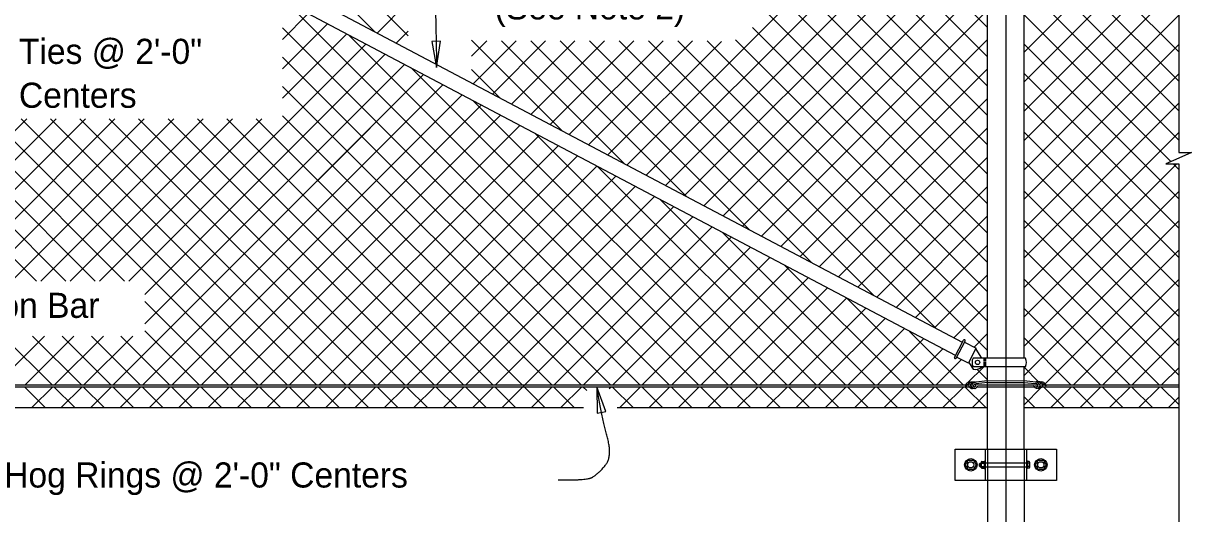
# Model space of a CAD drawing. Extents: x 0 to 41.1, y 0 to 25.9.
# Drawn here: x 6.74 to 16.11, y 16.37 to 20.31 of the extents above; entities that cross this region are included whole.
import ezdxf

# ---------------------------------------------------------------- set-up
doc = ezdxf.new("R2010")
doc.units = 0
for name, color, linetype in [('CL_Major', 7, 'Continuous'), ('Dimension', 7, 'Continuous'), ('Miscellaneous', 7, 'Continuous'), ('SteelMisc', 7, 'Continuous'), ('SteelMisc_h', 7, 'Continuous'), ('SupstrConc', 7, 'Continuous'), ('TextStructures', 7, 'Continuous')]:
    doc.layers.add(name, color=color, linetype=linetype)

msp = doc.modelspace()

# ---------------------------------------------------------------- linework, layer by layer
at = {"layer": 'CL_Major'}
msp.add_line((14.615, 25.0052), (14.615, 15.2584), dxfattribs=at)
at = {"layer": 'Dimension'}
for points in [[(16.002, 23.2265), (16.002, 21.2702), (16.1053, 21.2702), (16.002, 21.2252), (15.8987, 21.1802), (16.002, 21.1802), (16.002, 20.2867)], [(16.002, 20.2867), (16.002, 19.2689), (16.1053, 19.2689), (16.002, 19.2239), (15.8987, 19.1789), (16.002, 19.1789), (16.002, 16.9746)], [(16.002, 17.2246), (16.002, 15.3737), (16.1053, 15.3737), (16.002, 15.3287), (15.8987, 15.2837), (16.002, 15.2837), (16.002, 13.2829)]]:
    msp.add_lwpolyline(points, dxfattribs=at)
for points in [[(10.0503, 19.9529), (10.0815, 20.1618), (10.011, 20.1604)], [(11.336, 17.3912), (11.3376, 17.18), (11.4071, 17.1923)]]:
    msp.add_lwpolyline(points, close=True, dxfattribs=at)
for points in [[(6.6174, 20.081), (6.4865, 20.0669), (6.3036, 20.1341), (6.3121, 20.4608), (6.945, 21.4806)], [(10.4281, 20.8052), (10.1586, 20.8133), (10.0405, 20.6549), (10.0376, 20.5337), (10.0422, 20.3659), (10.0503, 19.9529)], [(11.0247, 16.6442), (11.2476, 16.6407), (11.3325, 16.6797), (11.4633, 16.8284), (11.3785, 17.1258), (11.336, 17.3911)]]:
    msp.add_open_spline(points, degree=2, dxfattribs=at)
at = {"layer": 'Miscellaneous'}
for p, q in [((6.7499, 23.0431), (9.5571, 20.2359)), ((6.9856, 23.0431), (9.8224, 20.2063)), ((10.5211, 23.0431), (14.4692, 19.095)), ((10.7568, 23.0431), (14.4692, 19.3307)), ((10.9925, 23.0431), (14.4692, 19.5664)), ((11.2282, 23.0431), (14.4692, 19.8021)), ((11.4639, 23.0431), (14.4692, 20.0378)), ((11.6996, 23.0431), (14.4692, 20.2735)), ((11.5767, 19.1686), (14.4692, 22.0611)), ((11.7309, 19.0871), (14.4692, 21.8254)), ((11.8851, 19.0056), (14.4692, 21.5897)), ((12.0393, 18.9241), (14.4692, 21.354)), ((14.7609, 21.318), (16.002, 20.0769)), ((14.7609, 20.0738), (16.002, 21.3149)), ((4.8859, 21.1359), (8.6158, 17.4059)), ((12.1936, 18.8426), (14.4692, 21.1183)), ((14.7609, 21.0823), (16.002, 19.8412)), ((14.7609, 19.8381), (16.002, 21.0792)), ((4.8859, 20.9002), (7.5472, 18.2388)), ((12.3478, 18.7611), (14.4692, 20.8826)), ((14.7609, 20.8466), (16.002, 19.6055)), ((14.7609, 19.6024), (16.002, 20.8435)), ((4.8859, 20.6644), (7.3115, 18.2388)), ((12.502, 18.6796), (14.4692, 20.6469)), ((12.6449, 20.6836), (14.4692, 18.8593)), ((14.7609, 20.6109), (16.002, 19.3698)), ((14.7609, 19.3667), (16.002, 20.6078)), ((4.8859, 20.4287), (7.0758, 18.2388)), ((8.845, 20.4766), (11.9157, 17.4059)), ((9.572, 20.228), (9.8224, 20.4784)), ((12.6214, 20.4714), (14.4692, 18.6236)), ((8.8145, 20.1777), (9.0206, 20.3838)), ((12.6562, 18.5982), (14.4692, 20.4112)), ((14.7609, 20.3752), (15.9395, 19.1966)), ((14.7609, 19.131), (16.002, 20.3721)), ((8.8145, 19.942), (9.1748, 20.3023)), ((8.8145, 20.2713), (11.68, 17.4059)), ((9.7262, 20.1465), (9.8224, 20.2427)), ((12.5832, 20.2739), (14.4692, 18.3879)), ((4.8876, 20.1913), (6.8401, 18.2388)), ((8.8145, 19.7063), (9.3291, 20.2208)), ((9.3449, 20.2124), (12.1514, 17.4059)), ((10.3288, 20.1713), (11.0567, 19.4434)), ((10.3288, 20.042), (10.4524, 20.1656)), ((10.343, 19.8205), (10.6881, 20.1656)), ((10.4973, 19.7391), (10.9238, 20.1656)), ((10.5702, 20.1656), (11.5565, 19.1793)), ((10.6515, 19.6576), (11.1595, 20.1656)), ((10.8057, 19.5761), (11.3952, 20.1656)), ((10.8059, 20.1656), (12.0564, 18.9151)), ((10.9599, 19.4946), (11.6309, 20.1656)), ((11.0416, 20.1656), (12.5562, 18.651)), ((11.1141, 19.4131), (11.8666, 20.1656)), ((11.2683, 19.3316), (12.1023, 20.1656)), ((11.2773, 20.1656), (13.0561, 18.3868)), ((11.4225, 19.2501), (12.3341, 20.1616)), ((11.513, 20.1656), (13.5559, 18.1227)), ((11.7487, 20.1656), (14.0558, 17.8585)), ((11.9844, 20.1656), (14.4692, 17.6808)), ((12.2201, 20.1656), (14.4692, 17.9165)), ((12.4479, 20.1735), (14.4692, 18.1522)), ((12.8104, 18.5167), (14.4692, 20.1755)), ((7.5828, 18.2388), (9.4833, 20.1393)), ((7.7103, 18.1306), (9.6375, 20.0578)), ((14.7609, 20.1395), (16.002, 18.8984)), ((14.7609, 18.8953), (16.002, 20.1364)), ((7.7103, 17.8949), (9.7917, 19.9763)), ((8.8145, 20.0356), (11.4443, 17.4059)), ((9.0917, 19.2763), (9.7917, 19.9763)), ((7.457, 17.4059), (9.9459, 19.8948)), ((9.0917, 19.0406), (9.9459, 19.8948)), ((9.8447, 19.9483), (12.3871, 17.4059)), ((10.3288, 19.9356), (10.5568, 19.7076)), ((12.9646, 18.4352), (14.4692, 19.9398)), ((14.7609, 19.9038), (16.002, 18.6627)), ((14.7609, 18.6596), (16.002, 19.9007)), ((7.6927, 17.4059), (10.1001, 19.8133)), ((8.8145, 19.7999), (11.2086, 17.4059)), ((9.0917, 18.8049), (10.1001, 19.8133)), ((7.9284, 17.4059), (10.2543, 19.7318)), ((10.3445, 19.6841), (12.6228, 17.4059)), ((13.1188, 18.3537), (14.4692, 19.7041)), ((8.1641, 17.4059), (10.4085, 19.6503)), ((14.7609, 19.6681), (16.002, 18.427)), ((14.7609, 18.4239), (16.002, 19.665)), ((5.7273, 18.5047), (6.7626, 19.54)), ((5.8187, 18.3603), (6.9983, 19.54)), ((5.9329, 18.2388), (7.234, 19.54)), ((6.1686, 18.2388), (7.4697, 19.54)), ((6.4043, 18.2388), (7.7055, 19.54)), ((6.64, 18.2388), (7.9412, 19.54)), ((6.7175, 19.54), (8.8515, 17.4059)), ((6.8757, 18.2388), (8.1769, 19.54)), ((6.9532, 19.54), (9.0872, 17.4059)), ((7.1114, 18.2388), (8.4126, 19.54)), ((7.1889, 19.54), (9.3229, 17.4059)), ((7.3471, 18.2388), (8.6483, 19.54)), ((7.4246, 19.54), (9.5586, 17.4059)), ((7.6603, 19.54), (9.7943, 17.4059)), ((7.896, 19.54), (10.03, 17.4059)), ((8.1317, 19.54), (10.2657, 17.4059)), ((8.3674, 19.54), (10.5014, 17.4059)), ((8.3998, 17.4059), (10.5627, 19.5688)), ((8.6031, 19.54), (10.7372, 17.4059)), ((8.8145, 19.5642), (10.9729, 17.4059)), ((8.6355, 17.4059), (10.717, 19.4873)), ((8.8712, 17.4059), (10.8712, 19.4059)), ((10.8444, 19.42), (12.8585, 17.4059)), ((13.273, 18.2722), (14.4692, 19.4684)), ((14.7609, 19.4324), (16.002, 18.1913)), ((14.7609, 18.1882), (16.002, 19.4293)), ((9.1069, 17.4059), (11.0254, 19.3244)), ((9.3426, 17.4059), (11.1796, 19.2429)), ((13.4272, 18.1907), (14.4692, 19.2327)), ((9.5783, 17.4059), (11.3338, 19.1614)), ((11.3442, 19.1559), (13.0942, 17.4059)), ((14.7609, 19.1967), (16.002, 17.9556)), ((14.7609, 17.9525), (15.9873, 19.1789)), ((15.9572, 19.1789), (16.002, 19.1341)), ((9.814, 17.4059), (11.488, 19.0799)), ((10.0497, 17.4059), (11.6422, 18.9984)), ((13.5814, 18.1092), (14.4692, 18.997)), ((14.7609, 18.961), (16.002, 17.7199)), ((14.7609, 17.7168), (16.002, 18.9578)), ((10.2854, 17.4059), (11.7964, 18.9169)), ((10.5211, 17.4059), (11.9506, 18.8354)), ((11.8441, 18.8917), (13.3299, 17.4059)), ((10.639, 17.2881), (12.1048, 18.7539)), ((13.7356, 18.0277), (14.4692, 18.7613)), ((10.9925, 17.4059), (12.2591, 18.6724)), ((14.7609, 18.7253), (16.002, 17.4842)), ((14.7609, 17.4811), (16.002, 18.7221)), ((11.2282, 17.4059), (12.4133, 18.5909)), ((12.3439, 18.6276), (13.5656, 17.4059)), ((11.4639, 17.4059), (12.5675, 18.5094)), ((13.8899, 17.9462), (14.4692, 18.5256)), ((14.7609, 18.4896), (15.8446, 17.4059)), ((14.9303, 17.4148), (16.002, 18.4864)), ((11.6996, 17.4059), (12.7217, 18.428)), ((11.9353, 17.4059), (12.8759, 18.3465)), ((12.8437, 18.3635), (13.8013, 17.4059)), ((14.0441, 17.8647), (14.4692, 18.2899)), ((12.1711, 17.4059), (13.0301, 18.265)), ((12.4068, 17.4059), (13.1843, 18.1835)), ((14.7609, 18.2539), (15.6089, 17.4059)), ((15.1572, 17.4059), (16.002, 18.2507)), ((12.6425, 17.4059), (13.3385, 18.102)), ((13.3436, 18.0993), (14.037, 17.4059)), ((7.7103, 18.0757), (8.3801, 17.4059)), ((12.8782, 17.4059), (13.4927, 18.0205)), ((14.1983, 17.7832), (14.4692, 18.0542)), ((14.7609, 18.0182), (15.3732, 17.4059)), ((15.3929, 17.4059), (16.002, 18.015)), ((13.1139, 17.4059), (13.647, 17.939)), ((7.7103, 17.84), (8.1444, 17.4059)), ((13.3496, 17.4059), (13.8012, 17.8575)), ((13.8434, 17.8352), (14.2727, 17.4059)), ((14.36, 17.7093), (14.4692, 17.8185)), ((6.5142, 17.4059), (6.9059, 17.7976)), ((6.5742, 17.7976), (6.9659, 17.4059)), ((6.7499, 17.4059), (7.1416, 17.7976)), ((6.8099, 17.7976), (7.2016, 17.4059)), ((6.9856, 17.4059), (7.3773, 17.7976)), ((7.0456, 17.7976), (7.4373, 17.4059)), ((7.2213, 17.4059), (7.613, 17.7976)), ((7.2813, 17.7976), (7.673, 17.4059)), ((7.517, 17.7976), (7.9087, 17.4059)), ((13.5853, 17.4059), (13.9554, 17.776)), ((14.7609, 17.7825), (15.1375, 17.4059)), ((15.6286, 17.4059), (16.002, 17.7793)), ((13.821, 17.4059), (14.1096, 17.6945)), ((14.0567, 17.4059), (14.2591, 17.6084)), ((14.3083, 17.4218), (14.4379, 17.5514)), ((14.3836, 17.5307), (14.4692, 17.4451)), ((14.7609, 17.5468), (14.8783, 17.4294)), ((15.8643, 17.4059), (16.002, 17.5436)), ((6.745, 17.3912), (6.9116, 17.2245)), ((6.8042, 17.2245), (6.9709, 17.3912)), ((6.9807, 17.3912), (7.1473, 17.2245)), ((7.0399, 17.2245), (7.2066, 17.3912)), ((7.2164, 17.3912), (7.383, 17.2245)), ((7.2756, 17.2245), (7.4423, 17.3912)), ((7.4521, 17.3912), (7.6187, 17.2245)), ((7.5113, 17.2245), (7.678, 17.3912)), ((7.6878, 17.3912), (7.8544, 17.2245)), ((7.747, 17.2245), (7.9137, 17.3912)), ((7.9235, 17.3912), (8.0901, 17.2245)), ((7.9827, 17.2245), (8.1494, 17.3912)), ((8.1592, 17.3912), (8.3258, 17.2245)), ((8.2184, 17.2245), (8.3851, 17.3912)), ((8.3949, 17.3912), (8.5615, 17.2245)), ((8.4541, 17.2245), (8.6208, 17.3912)), ((8.6306, 17.3912), (8.7972, 17.2245)), ((8.6898, 17.2245), (8.8565, 17.3912)), ((8.8663, 17.3912), (9.0329, 17.2245)), ((8.9255, 17.2245), (9.0922, 17.3912)), ((9.102, 17.3912), (9.2687, 17.2245)), ((9.1612, 17.2245), (9.3279, 17.3912)), ((9.3377, 17.3912), (9.5044, 17.2245)), ((9.3969, 17.2245), (9.5636, 17.3912)), ((9.5734, 17.3912), (9.7401, 17.2245)), ((9.6326, 17.2245), (9.7993, 17.3912)), ((9.8091, 17.3912), (9.9758, 17.2245)), ((9.8683, 17.2245), (10.035, 17.3912)), ((10.0448, 17.3912), (10.2115, 17.2245)), ((10.104, 17.2245), (10.2707, 17.3912)), ((10.2805, 17.3912), (10.4472, 17.2245)), ((10.3397, 17.2245), (10.5064, 17.3912)), ((10.5162, 17.3912), (10.6829, 17.2245)), ((10.5754, 17.2245), (10.7421, 17.3912)), ((10.7519, 17.3912), (10.9186, 17.2245)), ((10.8111, 17.2245), (10.9778, 17.3912)), ((10.9876, 17.3912), (11.1543, 17.2245)), ((11.0468, 17.2245), (11.2135, 17.3912)), ((11.2233, 17.3912), (11.2544, 17.36)), ((11.4351, 17.3771), (11.4492, 17.3912)), ((11.459, 17.3912), (11.6257, 17.2245)), ((11.5182, 17.2245), (11.6849, 17.3912)), ((11.6947, 17.3912), (11.8614, 17.2245)), ((11.7539, 17.2245), (11.9206, 17.3912)), ((11.9304, 17.3912), (12.0971, 17.2245)), ((11.9896, 17.2245), (12.1563, 17.3912)), ((12.1661, 17.3912), (12.3328, 17.2245)), ((12.2253, 17.2245), (12.392, 17.3912)), ((12.4018, 17.3912), (12.5685, 17.2245)), ((12.461, 17.2245), (12.6277, 17.3912)), ((12.6375, 17.3912), (12.8042, 17.2245)), ((12.6967, 17.2245), (12.8634, 17.3912)), ((12.8732, 17.3912), (13.0399, 17.2245)), ((12.9324, 17.2245), (13.0991, 17.3912)), ((13.1089, 17.3912), (13.2756, 17.2245)), ((13.1681, 17.2245), (13.3348, 17.3912)), ((13.3446, 17.3912), (13.5113, 17.2245)), ((13.4038, 17.2245), (13.5705, 17.3912)), ((13.5803, 17.3912), (13.747, 17.2245)), ((13.6396, 17.2245), (13.8062, 17.3912)), ((13.816, 17.3912), (13.9827, 17.2245)), ((13.8753, 17.2245), (14.0419, 17.3912)), ((14.0517, 17.3912), (14.2184, 17.2245)), ((14.111, 17.2245), (14.2776, 17.3912)), ((14.2874, 17.3912), (14.4541, 17.2245)), ((14.2924, 17.4059), (14.296, 17.4095)), ((14.3467, 17.2245), (14.4692, 17.3471)), ((14.7609, 17.2454), (14.8992, 17.3837)), ((14.9165, 17.3912), (15.0832, 17.2245)), ((14.9757, 17.2245), (15.1424, 17.3912)), ((15.1522, 17.3912), (15.3189, 17.2245)), ((15.2114, 17.2245), (15.3781, 17.3912)), ((15.3879, 17.3912), (15.5546, 17.2245)), ((15.4471, 17.2245), (15.6138, 17.3912)), ((15.6236, 17.3912), (15.7903, 17.2245)), ((15.6828, 17.2245), (15.8495, 17.3912)), ((15.8593, 17.3912), (16.002, 17.2485)), ((14.7641, 17.3078), (14.8475, 17.2245)), ((15.9185, 17.2245), (16.002, 17.3079)), ((14.4075, 16.7575), (14.4075, 16.7696)), ((14.4132, 16.7575), (14.4132, 16.7696))]:
    msp.add_line(p, q, dxfattribs=at)
at = {"layer": 'SteelMisc'}
for p, q in [((14.4692, 17.6192), (14.4692, 23.2644)), ((14.7609, 17.6192), (14.7609, 23.2644)), ((14.2677, 17.7466), (5.0181, 22.6346)), ((14.2117, 17.6406), (4.962, 22.5285)), ((14.2041, 17.6263), (14.2766, 17.7635)), ((14.216, 17.6201), (14.2885, 17.7572)), ((14.2843, 17.7493), (14.3786, 17.6995)), ((14.3149, 17.5789), (14.2206, 17.6287)), ((14.3149, 17.5789), (14.3786, 17.6995)), ((14.7722, 17.6193), (14.3525, 17.6193)), ((14.3744, 17.6914), (14.4213, 17.6197)), ((14.3184, 17.5855), (14.3531, 17.5323)), ((14.7721, 17.5514), (14.3525, 17.5514)), ((14.4349, 17.613), (14.4584, 17.613)), ((14.4349, 17.6032), (14.4584, 17.6032)), ((14.4349, 17.5914), (14.4584, 17.5914)), ((14.4349, 17.5797), (14.4584, 17.5797)), ((14.4349, 17.5688), (14.4584, 17.5688)), ((14.4349, 17.5593), (14.4584, 17.5593)), ((14.4692, 16.8894), (14.4692, 17.5514)), ((14.7609, 16.8894), (14.7609, 17.5514)), ((14.4692, 17.4385), (14.3743, 17.4274)), ((14.4692, 17.4385), (14.7604, 17.4402)), ((14.7604, 17.4402), (14.8547, 17.4291)), ((4.923, 17.3912), (14.3207, 17.3912)), ((4.9243, 17.4059), (14.2941, 17.4059)), ((14.304, 17.4059), (14.3172, 17.4059)), ((14.4692, 17.424), (14.3766, 17.4145)), ((14.3856, 17.3912), (14.4692, 17.3912)), ((14.387, 17.4059), (14.4692, 17.4059)), ((14.4692, 17.424), (14.7604, 17.4257)), ((14.7604, 17.4257), (14.8525, 17.4163)), ((14.7609, 17.4059), (14.8413, 17.4059)), ((14.7609, 17.3912), (14.8439, 17.3912)), ((14.9059, 17.3912), (16.002, 17.3912)), ((14.9116, 17.4059), (14.9269, 17.4059)), ((14.9353, 17.4059), (16.002, 17.4059)), ((14.2091, 16.8894), (15.021, 16.8894)), ((14.2091, 16.6394), (14.2091, 16.8894)), ((14.4484, 16.8894), (14.4484, 16.6394)), ((14.7817, 16.8894), (14.7817, 16.6394)), ((15.021, 16.8894), (15.021, 16.6394)), ((14.4047, 16.7724), (14.4103, 16.7789)), ((14.4047, 16.7547), (14.4047, 16.7724)), ((14.4103, 16.7789), (14.4168, 16.7789)), ((14.4103, 16.749), (14.4103, 16.7789)), ((14.4168, 16.7823), (14.4168, 16.7465)), ((14.4215, 16.7774), (14.4418, 16.7774)), ((14.4217, 16.7904), (14.4418, 16.7904)), ((14.4418, 16.7947), (14.4418, 16.734)), ((14.4418, 16.7947), (14.4484, 16.7947)), ((14.4418, 16.7904), (14.4418, 16.7384)), ((14.788, 16.7947), (14.782, 16.7947)), ((14.788, 16.7947), (14.788, 16.734)), ((14.8027, 16.7903), (14.788, 16.7903)), ((14.8028, 16.7773), (14.788, 16.7773)), ((14.8078, 16.745), (14.8078, 16.7838)), ((14.4047, 16.7547), (14.4103, 16.749)), ((14.4103, 16.749), (14.4168, 16.749)), ((14.4215, 16.7514), (14.4418, 16.7514)), ((14.4218, 16.7384), (14.4418, 16.7384)), ((14.4418, 16.734), (14.4484, 16.734)), ((14.788, 16.734), (14.782, 16.734)), ((14.8028, 16.7514), (14.788, 16.7514)), ((14.8027, 16.7384), (14.788, 16.7384)), ((15.021, 16.6394), (14.2091, 16.6394)), ((14.4692, 16.6394), (14.4692, 15.8894)), ((14.7609, 16.6394), (14.7609, 15.8894))]:
    msp.add_line(p, q, dxfattribs=at)
for points in [[(14.3124, 16.8019), (14.3557, 16.8019), (14.3774, 16.7644), (14.3557, 16.7269), (14.3124, 16.7269), (14.2907, 16.7644)], [(14.8744, 16.8019), (14.9177, 16.8019), (14.9394, 16.7644), (14.9177, 16.7269), (14.8744, 16.7269), (14.8527, 16.7644)]]:
    msp.add_lwpolyline(points, close=True, dxfattribs=at)
for centre, radius in [((14.3341, 16.7644), 0.05), ((14.3341, 16.7644), 0.025), ((14.896, 16.7644), 0.05), ((14.896, 16.7644), 0.025)]:
    msp.add_circle(centre, radius, dxfattribs=at)
for centre, radius, start, end in [((14.2827, 17.7605), 0.00673, 332.14902, 152.14902), ((14.2102, 17.6233), 0.00673, 152.14902, 332.14902), ((14.4234, 16.7838), 0.00674, 104.48908, 254.18889), ((14.4363, 16.7644), 0.0196, 138.62797, 221.37203), ((14.801, 16.7838), 0.00673, 285.7823, 75.54039), ((14.7881, 16.7644), 0.0196, 318.62797, 41.37203), ((14.4234, 16.7449), 0.00673, 105.7823, 255.54039), ((14.801, 16.7449), 0.00674, 284.48908, 74.18889)]:
    msp.add_arc(centre, radius, start, end, dxfattribs=at)
for centre, major_axis, ratio, start_param, end_param in [((14.4217, 17.5856), (-0.0776, 0), 0.957868, 5.810211, 6.75616), ((14.7031, 17.5855), (0.0776, 0), 0.957868, 5.807767, 6.754779), ((14.3697, 17.6006), (0.0647, -0.0342), 0.957868, 4.95193, 6.011789), ((14.3283, 17.3916), (0.0373, 0), 0.957868, 1.486836, 3.108042), ((14.3408, 17.4061), (0.023, 0), 0.957868, 1.29026, 2.970541), ((14.3595, 17.4007), (0.0295, 0), 0.957868, 1.220941, 4.039556), ((14.8556, 17.4043), (0.0303, -0.0108), 0.724765, 6.241815, 8.212701), ((14.8691, 17.4025), (-0.0295, 0), 0.957868, 2.243629, 5.062245), ((14.8879, 17.4079), (-0.023, 0), 0.957868, 3.312645, 4.992926), ((14.9004, 17.3934), (-0.0373, 0), 0.957868, 3.175144, 4.79635), ((14.3494, 17.3519), (-0.0724, 0), 0.957868, 5.162149, 5.652106), ((14.3419, 17.4036), (-0.0249, 0), 0.957868, 6.009018, 7.089857), ((14.3433, 17.3996), (0.0231, 0), 0.957868, 3.779554, 4.879821), ((14.373, 17.4025), (-0.0303, -0.0108), 0.724765, 4.35367, 6.324556), ((14.3494, 17.3939), (0.0206, -0.0021), 0.798607, 4.32653, 5.220153), ((14.3629, 17.3939), (0.0206, -0.0021), 0.798607, 3.333154, 5.220153), ((14.3697, 17.3985), (-0.0139, 0), 0.957868, 5.22362, 6.905413), ((14.364, 17.3961), (-0.00795, 0), 0.957868, 6.140374, 9.314262), ((14.3781, 17.3896), (-0.0259, 0), 0.957868, 4.777514, 5.62749), ((14.3624, 17.4019), (0.0119, 0), 0.957868, 5.725876, 7.416677), ((14.3555, 17.4127), (0.0391, 0), 0.957868, 5.082588, 5.41974), ((14.3624, 17.4019), (0.0119, 0), 0.957868, 5.639684, 5.723117), ((14.3626, 17.4006), (0.0251, 0), 0.957868, 5.531357, 6.227833), ((14.3626, 17.4006), (0.0251, 0), 0.957868, 0.407687, 0.609214), ((14.8661, 17.4024), (-0.0251, 0), 0.957868, 0.055352, 0.751829), ((14.8661, 17.4024), (-0.0251, 0), 0.957868, 5.673972, 5.875498), ((14.8732, 17.4144), (-0.0391, 0), 0.957868, 0.863445, 1.200597), ((14.8506, 17.3914), (0.0259, 0), 0.957868, 0.655696, 1.505671), ((14.8663, 17.4036), (-0.0119, 0), 0.957868, 5.149694, 6.840495), ((14.8663, 17.4036), (-0.0119, 0), 0.957868, 0.560069, 0.643501), ((14.8646, 17.3979), (0.00795, 0), 0.957868, 3.252108, 6.425997), ((14.8658, 17.3957), (-0.0206, -0.0021), 0.798607, 1.063032, 2.950031), ((14.859, 17.4002), (0.0139, 0), 0.957868, 5.660958, 7.342751), ((14.8792, 17.3957), (-0.0206, -0.0021), 0.798607, 1.063032, 1.956656), ((14.8853, 17.4014), (-0.0231, 0), 0.957868, 1.403365, 2.503632), ((14.8867, 17.4054), (0.0249, 0), 0.957868, 5.476514, 6.557353), ((14.8792, 17.3537), (0.0724, 0), 0.957868, 0.631079, 1.121037)]:
    msp.add_ellipse(centre, major_axis=major_axis, ratio=ratio, start_param=start_param, end_param=end_param, dxfattribs=at)
msp.add_ellipse((14.3884, 17.586), major_axis=(0.0178, 0), ratio=0.957868, dxfattribs=at)
at = {"layer": 'SteelMisc_h'}
for p, q in [((14.4692, 17.4059), (14.7609, 17.4059)), ((14.4692, 17.3912), (14.7609, 17.3912)), ((14.4692, 16.8894), (14.4692, 16.6394)), ((14.7609, 16.8894), (14.7609, 16.6394)), ((14.7817, 16.7789), (14.4168, 16.7789)), ((14.4168, 16.749), (14.7817, 16.749))]:
    msp.add_line(p, q, dxfattribs=at)
at = {"layer": 'SupstrConc'}
for p, q in [((4.7609, 17.2245), (11.2293, 17.2245)), ((11.4981, 17.2245), (14.4692, 17.2245)), ((14.7609, 17.2245), (16.002, 17.2245))]:
    msp.add_line(p, q, dxfattribs=at)

# ---------------------------------------------------------------- texts
at = {"layer": 'Dimension'}
for s, p in [('Ties @ 2\'-0" ', (6.6999, 19.9805)), ('Centers', (6.6999, 19.6285))]:
    msp.add_text(s, height=0.2016, dxfattribs=at).set_placement(p)
at = {"layer": 'TextStructures'}
for s, p in [('(See Note 2)', (10.5146, 20.3375)), ('Tension Bar', (5.892, 17.9432)), ('Hog Rings @ 2\'-0" Centers', (6.5816, 16.5823))]:
    msp.add_text(s, height=0.2016, dxfattribs=at).set_placement(p)

doc.saveas('drawing.dxf')
